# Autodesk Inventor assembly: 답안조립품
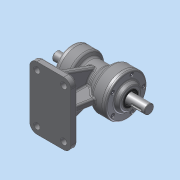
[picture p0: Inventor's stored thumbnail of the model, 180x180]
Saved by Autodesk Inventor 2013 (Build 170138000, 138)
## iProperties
Created: 2015-08
Part Number: 답안조립품
Document SubType Name: Assembly
Designer: Administrator
Author: Administrator
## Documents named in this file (10)
- C:\Users\Administrator\Desktop\450806V1022\답안조립품.iam
- C:\Users\Administrator\Desktop\450806V1022\본체.ipt
- C:\Users\Administrator\Desktop\450806V1022\M4x0.5.ipt
- C:\Users\Administrator\Desktop\450806V1022\뒤커버.ipt
- C:\Users\Administrator\Desktop\450806V1022\베어링 6203.ipt
- C:\Users\Administrator\Desktop\450806V1022\베어링 6205.ipt
- C:\Users\Administrator\Desktop\450806V1022\앞커버.ipt
- C:\Users\Administrator\Desktop\450806V1022\오일실 .ipt
- 오일실 .ipt
- C:\Users\Administrator\Desktop\450806V1022\축.ipt
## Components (10 placed, 1 different names)
1. M4x0.5:2
2. M4x0.5:3
3. M4x0.5:4
4. M4x0.5:5
5. M4x0.5:6
6. M4x0.5:1
7. M4x0.5:7
8. M4x0.5:8
9. M4x0.5:9
10. M4x0.5:10
